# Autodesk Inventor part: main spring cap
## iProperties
Created: 2006-04
Part Number: main spring cap
Document SubType Name: Modeling
Designer: Калинин
Author: Калинин
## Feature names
1. Вращение1 [Revolution]
2. Оболочка1
